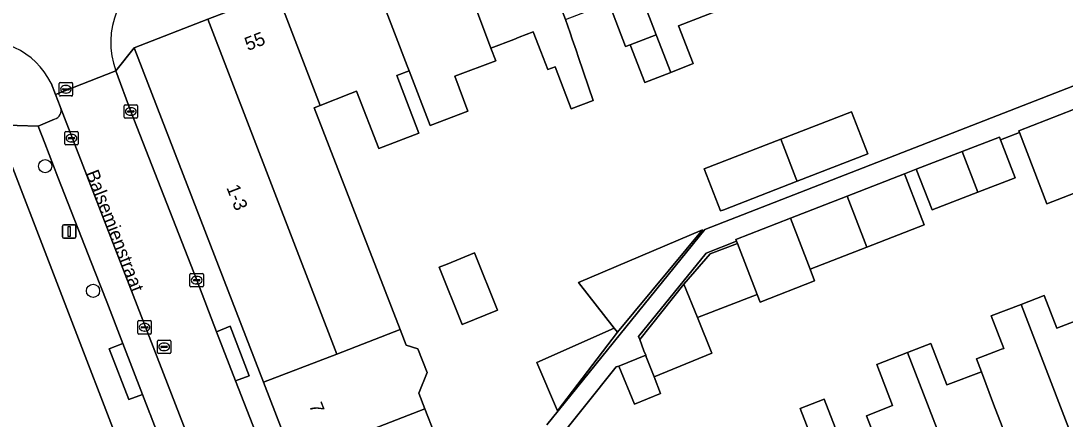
# Model space of a CAD drawing. Extents: x 161692 to 162379, y 380760 to 381678.
# Drawn here: x 161835.2 to 161912.8, y 381153.5 to 381183.1 of the extents above; entities that cross this region are included whole.
import ezdxf

# ---------------------------------------------------------------- set-up
doc = ezdxf.new("R2010")
doc.units = 0
for name, color, linetype in [('IMGEO_Boom', 7, 'Continuous'), ('IMGEO_Erf', 7, 'Continuous'), ('IMGEO_Kolk', 7, 'Continuous'), ('IMGEO_Lichtmast', 7, 'Continuous'), ('IMGEO_Openbare_ruimte_label', 7, 'Continuous'), ('IMGEO_Pand', 7, 'Continuous'), ('IMGEO_Pand_nummerreeks', 7, 'Continuous'), ('IMGEO_Parkeervlak_open', 7, 'Continuous'), ('IMGEO_Rijbaan_lokaal_open', 7, 'Continuous'), ('IMGEO_Rioolput', 7, 'Continuous'), ('IMGEO_Voetpad_open', 7, 'Continuous')]:
    doc.layers.add(name, color=color, linetype=linetype)

msp = doc.modelspace()

# ---------------------------------------------------------------- linework, layer by layer
at = {"layer": 'IMGEO_Boom'}
for centre in [(161836.982, 381172.296), (161840.539, 381163.033)]:
    msp.add_circle(centre, 0.489, dxfattribs=at)
at = {"layer": 'IMGEO_Erf'}
for points in [[(161887.347, 381183.967), (161884.084, 381182.701), (161885.163, 381179.907), (161883.498, 381179.26), (161881.565, 381178.51), (161880.481, 381181.302), (161880.149, 381181.173), (161878.886, 381184.426)], [(161875.683, 381183.185), (161876.021, 381182.188), (161876.181, 381181.716), (161876.457, 381180.901), (161876.644, 381180.352), (161877.72, 381177.175), (161876.108, 381176.549), (161874.895, 381179.673), (161874.372, 381179.47), (161873.851, 381180.812), (161873.282, 381182.277), (161872.232, 381181.869), (161871.822, 381181.71), (161870.13, 381181.053), (161870.484, 381180.109), (161867.441, 381178.968), (161868.413, 381176.374), (161865.604, 381175.321), (161864.044, 381179.374), (161863.12, 381179.015), (161864.764, 381174.744), (161861.798, 381173.593), (161860.142, 381177.859), (161859.691, 381177.684), (161857.428, 381176.805), (161856.984, 381176.633), (161863.374, 381160.161), (161863.819, 381159.013), (161864.704, 381158.737), (161865.389, 381156.97), (161864.766, 381155.425), (161865.216, 381154.264), (161865.926, 381152.436)], [(161874.298, 381153.095), (161886.039, 381167.594), (161916.769, 381179.551)], [(161854.96, 381119.298), (161852.88, 381124.681), (161833.302, 381175.355), (161830.972, 381176.303), (161782.92, 381157.51), (161766.802, 381160.481), (161766.378, 381160.559)], [(161915.559, 381171.074), (161911.474, 381169.496), (161909.428, 381174.795), (161908.019, 381174.254), (161909.11, 381171.437), (161906.334, 381170.361), (161902.933, 381169.043), (161901.766, 381172.062), (161900.896, 381171.725), (161902.063, 381168.706), (161902.352, 381167.93), (161898.092, 381166.28), (161893.863, 381164.642), (161894.2, 381163.77), (161890.147, 381162.199), (161889.925, 381162.773), (161885.48, 381161.051), (161886.553, 381158.395), (161882.26, 381156.64), (161882.731, 381155.417), (161880.796, 381154.626), (161879.645, 381157.442), (161879.432, 381157.38), (161874.741, 381151.504)], [(161899.206, 381150.813), (161898.066, 381153.763), (161900.001, 381154.51), (161898.818, 381157.573), (161901.113, 381158.46), (161902.848, 381159.131), (161904.04, 381156.046), (161904.116, 381156.075), (161906.602, 381157.017), (161906.233, 381157.993), (161907.863, 381158.611), (161908.093, 381158.698), (161908.262, 381158.762), (161907.334, 381161.171), (161909.551, 381162.027), (161911.285, 381162.697), (161912.225, 381160.266), (161914.674, 381161.212)], [(161893.937, 381152.191), (161893.123, 381154.298), (161894.921, 381154.993), (161895.735, 381152.886)]]:
    msp.add_lwpolyline(points, dxfattribs=at)
for points in [[(161896.945, 381176.323), (161898.147, 381173.214), (161892.908, 381171.173), (161887.438, 381169.06), (161887.202, 381168.969), (161885.995, 381172.096), (161891.7, 381174.299)], [(161879.533, 381159.957), (161875.084, 381154.124), (161873.533, 381157.706), (161879.286, 381160.272), (161876.651, 381163.642), (161885.853, 381167.576)], [(161884.481, 381163.524), (161886.441, 381165.776), (161888.458, 381166.558), (161888.395, 381166.721), (161886.13, 381165.843), (161881.107, 381159.64), (161881.194, 381159.413)], [(161868.916, 381165.851), (161870.627, 381161.602), (161867.991, 381160.54), (161866.279, 381164.787), (161866.871, 381165.026)]]:
    msp.add_lwpolyline(points, close=True, dxfattribs=at)
at = {"layer": 'IMGEO_Kolk'}
for p, q in [((161842.847, 381175.926), (161842.847, 381176.778)), ((161842.922, 381176.852), (161843.774, 381176.852)), ((161843.848, 381176.778), (161843.848, 381175.926)), ((161843.106, 381176.346), (161843.106, 381176.358)), ((161843.544, 381176.309), (161843.146, 381176.309)), ((161843.149, 381176.395), (161843.547, 381176.395)), ((161843.358, 381176.072), (161843.333, 381176.072)), ((161843.335, 381176.632), (161843.36, 381176.632)), ((161843.59, 381176.358), (161843.59, 381176.346)), ((161843.774, 381175.852), (161842.922, 381175.852)), ((161838.438, 381173.943), (161838.438, 381174.795)), ((161838.513, 381174.869), (161839.365, 381174.869)), ((161838.926, 381174.649), (161838.951, 381174.649)), ((161839.439, 381174.795), (161839.439, 381173.943)), ((161839.365, 381173.869), (161838.513, 381173.869)), ((161838.697, 381174.363), (161838.697, 381174.375)), ((161839.135, 381174.326), (161838.737, 381174.326)), ((161838.74, 381174.412), (161839.138, 381174.412)), ((161838.949, 381174.089), (161838.924, 381174.089)), ((161839.181, 381174.375), (161839.181, 381174.363)), ((161847.746, 381163.4), (161847.746, 381164.252)), ((161847.821, 381164.326), (161848.673, 381164.326)), ((161848.005, 381163.82), (161848.005, 381163.832)), ((161848.443, 381163.783), (161848.045, 381163.783)), ((161848.048, 381163.869), (161848.446, 381163.869)), ((161848.234, 381164.106), (161848.259, 381164.106)), ((161848.489, 381163.832), (161848.489, 381163.82)), ((161848.747, 381164.252), (161848.747, 381163.4)), ((161848.673, 381163.326), (161847.821, 381163.326)), ((161848.257, 381163.546), (161848.232, 381163.546)), ((161843.871, 381159.902), (161843.871, 381160.754)), ((161843.946, 381160.828), (161844.798, 381160.828)), ((161844.359, 381160.608), (161844.384, 381160.608)), ((161844.872, 381160.754), (161844.872, 381159.902)), ((161844.798, 381159.828), (161843.946, 381159.828)), ((161844.13, 381160.322), (161844.13, 381160.334)), ((161844.568, 381160.285), (161844.17, 381160.285)), ((161844.173, 381160.371), (161844.571, 381160.371)), ((161844.382, 381160.048), (161844.357, 381160.048)), ((161844.614, 381160.334), (161844.614, 381160.322))]:
    msp.add_line(p, q, dxfattribs=at)
for points in [[(161842.847, 381175.926), (161842.847, 381176.778)], [(161842.922, 381176.852), (161843.774, 381176.852)], [(161843.848, 381176.778), (161843.848, 381175.926)], [(161843.774, 381175.852), (161842.922, 381175.852)], [(161838.438, 381173.943), (161838.438, 381174.795)], [(161838.513, 381174.869), (161839.365, 381174.869)], [(161839.439, 381174.795), (161839.439, 381173.943)], [(161839.365, 381173.869), (161838.513, 381173.869)], [(161847.746, 381163.4), (161847.746, 381164.252)], [(161847.821, 381164.326), (161848.673, 381164.326)], [(161848.747, 381164.252), (161848.747, 381163.4)], [(161848.673, 381163.326), (161847.821, 381163.326)], [(161843.871, 381159.902), (161843.871, 381160.754)], [(161843.946, 381160.828), (161844.798, 381160.828)], [(161844.872, 381160.754), (161844.872, 381159.902)], [(161844.798, 381159.828), (161843.946, 381159.828)]]:
    msp.add_lwpolyline(points, dxfattribs=at)
for centre, radius, start, end in [((161842.924, 381176.776), 0.0765, 91.55205, 178.44795), ((161842.924, 381176.776), 0.0765, 91.55205, 178.44795), ((161843.772, 381176.776), 0.0765, 1.55205, 88.44795), ((161843.772, 381176.776), 0.0765, 1.55205, 88.44795), ((161843.146, 381176.355), 0.0403, 85.87752, 175.75265), ((161843.143, 381176.345), 0.0366, 178.93798, 274.71019), ((161843.547, 381176.352), 0.043, 264.86636, 352.45326), ((161843.551, 381176.357), 0.0386, 1.73085, 96.63898), ((161842.924, 381175.928), 0.0765, 181.55205, 268.44795), ((161842.924, 381175.928), 0.0765, 181.55205, 268.44795), ((161843.772, 381175.928), 0.0765, 271.55205, 358.44795), ((161843.772, 381175.928), 0.0765, 271.55205, 358.44795), ((161838.515, 381174.793), 0.0765, 91.55205, 178.44795), ((161838.515, 381174.793), 0.0765, 91.55205, 178.44795), ((161839.363, 381174.793), 0.0765, 1.55205, 88.44795), ((161839.363, 381174.793), 0.0765, 1.55205, 88.44795), ((161838.515, 381173.945), 0.0765, 181.55205, 268.44795), ((161838.515, 381173.945), 0.0765, 181.55205, 268.44795), ((161838.737, 381174.372), 0.0403, 85.87752, 175.75265), ((161838.734, 381174.362), 0.0366, 178.93798, 274.71019), ((161839.138, 381174.369), 0.043, 264.86636, 352.45326), ((161839.142, 381174.374), 0.0386, 1.73085, 96.63898), ((161839.363, 381173.945), 0.0765, 271.55205, 358.44795), ((161839.363, 381173.945), 0.0765, 271.55205, 358.44795), ((161847.823, 381164.25), 0.0765, 91.55205, 178.44795), ((161847.823, 381164.25), 0.0765, 91.55205, 178.44795), ((161848.045, 381163.829), 0.0403, 85.87752, 175.75265), ((161848.042, 381163.819), 0.0366, 178.93798, 274.71019), ((161848.446, 381163.826), 0.043, 264.86636, 352.45326), ((161848.45, 381163.831), 0.0386, 1.73085, 96.63898), ((161848.671, 381164.25), 0.0765, 1.55205, 88.44795), ((161848.671, 381164.25), 0.0765, 1.55205, 88.44795), ((161847.823, 381163.402), 0.0765, 181.55205, 268.44795), ((161847.823, 381163.402), 0.0765, 181.55205, 268.44795), ((161848.671, 381163.402), 0.0765, 271.55205, 358.44795), ((161848.671, 381163.402), 0.0765, 271.55205, 358.44795), ((161843.948, 381160.752), 0.0765, 91.55205, 178.44795), ((161843.948, 381160.752), 0.0765, 91.55205, 178.44795), ((161844.796, 381160.752), 0.0765, 1.55205, 88.44795), ((161844.796, 381160.752), 0.0765, 1.55205, 88.44795), ((161843.948, 381159.904), 0.0765, 181.55205, 268.44795), ((161843.948, 381159.904), 0.0765, 181.55205, 268.44795), ((161844.17, 381160.331), 0.0403, 85.87752, 175.75265), ((161844.167, 381160.321), 0.0366, 178.93798, 274.71019), ((161844.571, 381160.328), 0.043, 264.86636, 352.45326), ((161844.575, 381160.333), 0.0386, 1.73085, 96.63898), ((161844.796, 381159.904), 0.0765, 271.55205, 358.44795), ((161844.796, 381159.904), 0.0765, 271.55205, 358.44795)]:
    msp.add_arc(centre, radius, start, end, dxfattribs=at)
for centre, major_axis, ratio, start_param, end_param in [((161843.334, 381176.352), (-0.387, 0.002), 0.722429, 4.712389, 7.853982), ((161843.359, 381176.352), (-0.39, 0.002), 0.717154, 1.570796, 4.712389), ((161838.925, 381174.369), (-0.387, 0.002), 0.722429, 4.712389, 7.853982), ((161838.95, 381174.369), (-0.39, 0.002), 0.717154, 1.570796, 4.712389), ((161848.233, 381163.826), (-0.387, 0.002), 0.722429, 4.712389, 7.853982), ((161848.258, 381163.826), (-0.39, 0.002), 0.717154, 1.570796, 4.712389), ((161844.358, 381160.328), (-0.387, 0.002), 0.722429, 4.712389, 7.853982), ((161844.383, 381160.328), (-0.39, 0.002), 0.717154, 1.570796, 4.712389)]:
    msp.add_ellipse(centre, major_axis=major_axis, ratio=ratio, start_param=start_param, end_param=end_param, dxfattribs=at)
at = {"layer": 'IMGEO_Lichtmast'}
for p, q in [((161838.274, 381167.04), (161838.274, 381167.84)), ((161838.274, 381167.84), (161838.274, 381167.04)), ((161838.374, 381167.94), (161839.164, 381167.94)), ((161839.164, 381167.94), (161838.374, 381167.94)), ((161839.264, 381167.84), (161839.264, 381167.04)), ((161839.264, 381167.04), (161839.264, 381167.84)), ((161839.164, 381166.94), (161838.374, 381166.94)), ((161838.374, 381166.94), (161839.164, 381166.94))]:
    msp.add_line(p, q, dxfattribs=at)
msp.add_lwpolyline([(161838.694, 381167.815), (161838.844, 381167.815), (161838.844, 381167.065), (161838.694, 381167.065), (161838.694, 381167.815)], dxfattribs=at)
for centre, start, end in [((161838.374, 381167.84), 90, 180), ((161838.374, 381167.84), 90, 180), ((161839.164, 381167.84), 0, 90), ((161839.164, 381167.84), 360, 90), ((161838.374, 381167.04), 180, 270), ((161838.374, 381167.04), 180, 270), ((161839.164, 381167.04), 270, 0), ((161839.164, 381167.04), 270, 0)]:
    msp.add_arc(centre, 0.1, start, end, dxfattribs=at)
at = {"layer": 'IMGEO_Pand'}
for points in [[(161883.425, 381195.727), (161882.9, 381195.524), (161882.325, 381195.986), (161880.061, 381195.107), (161879.937, 381194.305), (161877.981, 381193.546), (161882.172, 381182.693), (161882.419, 381182.054), (161883.498, 381179.26), (161885.163, 381179.907), (161884.084, 381182.701), (161887.347, 381183.967), (161886.094, 381187.199), (161886.637, 381187.41)], [(161877.981, 381193.546), (161875.697, 381192.659), (161875.012, 381193.209), (161872.965, 381192.415), (161872.83, 381191.539), (161872.505, 381191.413), (161875.683, 381183.185), (161877.356, 381183.833), (161877.67, 381183.955), (161878.662, 381184.339), (161878.886, 381184.426), (161880.149, 381181.173), (161880.481, 381181.302), (161882.419, 381182.054), (161882.172, 381182.693)], [(161872.505, 381191.413), (161870.281, 381190.549), (161869.541, 381191.144), (161866.752, 381190.062), (161870.13, 381181.053), (161871.822, 381181.71), (161872.232, 381181.869), (161873.282, 381182.277), (161873.851, 381180.812), (161874.372, 381179.47), (161874.895, 381179.673), (161876.108, 381176.549), (161877.72, 381177.175), (161876.644, 381180.352), (161876.457, 381180.901), (161876.181, 381181.716), (161876.021, 381182.188), (161875.683, 381183.185)], [(161866.752, 381190.062), (161860.818, 381187.759), (161863.904, 381179.738), (161864.044, 381179.374), (161865.604, 381175.321), (161868.413, 381176.374), (161867.441, 381178.968), (161870.484, 381180.109), (161870.13, 381181.053)], [(161860.818, 381187.759), (161854.202, 381185.191), (161857.428, 381176.805), (161859.691, 381177.684), (161860.142, 381177.859), (161861.798, 381173.593), (161864.764, 381174.744), (161863.12, 381179.015), (161864.044, 381179.374), (161863.904, 381179.738)], [(161849.069, 381183.199), (161858.668, 381158.344), (161863.374, 381160.161), (161856.984, 381176.633), (161857.428, 381176.805), (161854.202, 381185.191)], [(161853.223, 381156.241), (161858.668, 381158.344), (161849.069, 381183.199), (161843.607, 381181.079)], [(161882.419, 381182.054), (161880.481, 381181.302), (161881.565, 381178.51), (161883.498, 381179.26)], [(161891.7, 381174.299), (161891.868, 381173.864), (161892.816, 381171.412), (161892.908, 381171.173), (161898.147, 381173.214), (161896.945, 381176.323)], [(161913.463, 381176.501), (161909.378, 381174.923), (161909.428, 381174.795), (161911.474, 381169.496), (161915.559, 381171.074)], [(161908.019, 381174.254), (161907.941, 381174.454), (161905.169, 381173.38), (161906.334, 381170.361), (161909.11, 381171.437)], [(161891.868, 381173.864), (161891.7, 381174.299), (161885.995, 381172.096), (161887.202, 381168.969), (161887.438, 381169.06), (161892.908, 381171.173), (161892.816, 381171.412)], [(161905.169, 381173.38), (161901.766, 381172.062), (161902.933, 381169.043), (161906.334, 381170.361)], [(161900.896, 381171.725), (161896.628, 381170.07), (161898.092, 381166.28), (161902.352, 381167.93), (161902.063, 381168.706)], [(161896.628, 381170.07), (161892.399, 381168.431), (161893.863, 381164.642), (161898.092, 381166.28)], [(161892.399, 381168.431), (161888.341, 381166.859), (161888.395, 381166.721), (161888.458, 381166.558), (161889.925, 381162.773), (161890.147, 381162.199), (161894.2, 381163.77), (161893.863, 381164.642)], [(161879.286, 381160.272), (161879.533, 381159.957), (161885.853, 381167.576), (161876.651, 381163.642)], [(161888.458, 381166.558), (161886.441, 381165.776), (161884.481, 381163.524), (161885.48, 381161.051), (161889.925, 381162.773)], [(161866.279, 381164.787), (161867.991, 381160.54), (161870.627, 381161.602), (161868.916, 381165.851), (161866.871, 381165.026)], [(161885.48, 381161.051), (161884.481, 381163.524), (161881.194, 381159.413), (161881.511, 381158.588), (161881.638, 381158.257), (161881.681, 381158.146), (161882.26, 381156.64), (161886.553, 381158.395)], [(161909.551, 381162.027), (161907.334, 381161.171), (161908.262, 381158.762), (161908.093, 381158.698), (161907.863, 381158.611), (161906.233, 381157.993), (161906.602, 381157.017), (161907.51, 381154.621), (161910.252, 381147.53), (161914.14, 381149.033), (161914.356, 381148.475), (161914.726, 381148.618)], [(161914.674, 381161.212), (161912.225, 381160.266), (161911.285, 381162.697), (161909.551, 381162.027), (161914.726, 381148.618), (161918.913, 381150.237), (161916.157, 381157.372)], [(161853.223, 381156.241), (161855.451, 381150.483), (161865.216, 381154.264), (161864.766, 381155.425), (161865.389, 381156.97), (161864.704, 381158.737), (161863.819, 381159.013), (161863.374, 381160.161), (161858.668, 381158.344)], [(161879.533, 381159.957), (161879.286, 381160.272), (161873.533, 381157.706), (161875.084, 381154.124)], [(161906.602, 381157.017), (161904.116, 381156.075), (161904.04, 381156.046), (161902.848, 381159.131), (161901.113, 381158.46), (161902.3, 381155.387), (161906.184, 381145.333), (161910.462, 381146.987), (161910.252, 381147.53), (161907.51, 381154.621)], [(161882.26, 381156.64), (161881.681, 381158.146), (161881.638, 381158.257), (161879.645, 381157.442), (161880.796, 381154.626), (161882.731, 381155.417)], [(161906.184, 381145.333), (161902.3, 381155.387), (161901.113, 381158.46), (161898.818, 381157.573), (161900.001, 381154.51), (161898.066, 381153.763), (161899.206, 381150.813), (161901.955, 381143.698)], [(161865.216, 381154.264), (161855.451, 381150.483), (161857.147, 381146.103), (161858.29, 381146.546), (161858.163, 381146.874), (161862.825, 381148.683), (161864.611, 381149.376), (161866.786, 381150.22), (161866.117, 381151.943), (161865.926, 381152.436)], [(161897.834, 381142.104), (161901.955, 381143.698), (161899.206, 381150.813), (161896.884, 381149.915), (161895.735, 381152.886), (161894.921, 381154.993), (161893.123, 381154.298), (161893.937, 381152.191)]]:
    msp.add_lwpolyline(points, close=True, dxfattribs=at)
at = {"layer": 'IMGEO_Parkeervlak_open'}
for points in [[(161855.826, 381131.012), (161838.128, 381176.641)], [(161837.683, 381175.784), (161836.452, 381175.254), (161836.947, 381173.989), (161837.932, 381171.471), (161840.67, 381164.477), (161841.558, 381162.207), (161842.766, 381159.12), (161844.228, 381155.33), (161844.771, 381153.925), (161844.787, 381153.884), (161845.637, 381151.683), (161849.329, 381142.123), (161850.18, 381139.921), (161853.234, 381132.015), (161853.712, 381130.777), (161854.94, 381131.274)]]:
    msp.add_lwpolyline(points, dxfattribs=at)
msp.add_arc((161837.48, 381176.433), 0.68, 287.35328, 17.76524, dxfattribs=at)
at = {"layer": 'IMGEO_Rijbaan_lokaal_open'}
for points in [[(161837.414, 381178.445), (161837.736, 381177.625), (161842.227, 381179.366)], [(161851.128, 381156.352), (161849.716, 381159.992), (161848.247, 381163.826), (161843.348, 381176.352), (161842.227, 381179.366), (161837.736, 381177.625), (161838.086, 381176.732), (161838.128, 381176.641), (161855.826, 381131.012)], [(161855.889, 381130.847), (161856.238, 381129.843), (161860.811, 381131.453), (161859.931, 381133.78), (161854.512, 381147.731), (161851.128, 381156.352)]]:
    msp.add_lwpolyline(points, dxfattribs=at)
for centre, radius, start, end in [((161847.948, 381181.477), 6.098, 114.76344, 200.24814), ((161832.316, 381175.959), 5.672, 26.00177, 103.52384)]:
    msp.add_arc(centre, radius, start, end, dxfattribs=at)
at = {"layer": 'IMGEO_Rioolput'}
for p, q in [((161838.02, 381177.577), (161838.02, 381178.429)), ((161838.095, 381178.503), (161838.947, 381178.503)), ((161839.021, 381178.429), (161839.021, 381177.577)), ((161838.279, 381177.997), (161838.279, 381178.009)), ((161838.717, 381177.96), (161838.319, 381177.96)), ((161838.322, 381178.046), (161838.72, 381178.046)), ((161838.531, 381177.723), (161838.506, 381177.723)), ((161838.508, 381178.283), (161838.533, 381178.283)), ((161838.763, 381178.009), (161838.763, 381177.997)), ((161838.947, 381177.503), (161838.095, 381177.503)), ((161845.324, 381158.453), (161845.324, 381159.305)), ((161845.399, 381159.379), (161846.251, 381159.379)), ((161845.626, 381158.922), (161846.024, 381158.922)), ((161845.812, 381159.159), (161845.837, 381159.159)), ((161846.325, 381159.305), (161846.325, 381158.453)), ((161846.251, 381158.379), (161845.399, 381158.379)), ((161845.583, 381158.873), (161845.583, 381158.885)), ((161846.021, 381158.836), (161845.623, 381158.836)), ((161845.835, 381158.599), (161845.81, 381158.599)), ((161846.067, 381158.885), (161846.067, 381158.873))]:
    msp.add_line(p, q, dxfattribs=at)
for points in [[(161838.02, 381177.577), (161838.02, 381178.429)], [(161838.095, 381178.503), (161838.947, 381178.503)], [(161839.021, 381178.429), (161839.021, 381177.577)], [(161838.947, 381177.503), (161838.095, 381177.503)], [(161845.324, 381158.453), (161845.324, 381159.305)], [(161845.399, 381159.379), (161846.251, 381159.379)], [(161846.325, 381159.305), (161846.325, 381158.453)], [(161846.251, 381158.379), (161845.399, 381158.379)]]:
    msp.add_lwpolyline(points, dxfattribs=at)
for centre, radius, start, end in [((161838.097, 381178.427), 0.0765, 91.55205, 178.44795), ((161838.097, 381178.427), 0.0765, 91.55205, 178.44795), ((161838.945, 381178.427), 0.0765, 1.55205, 88.44795), ((161838.945, 381178.427), 0.0765, 1.55205, 88.44795), ((161838.097, 381177.579), 0.0765, 181.55205, 268.44795), ((161838.097, 381177.579), 0.0765, 181.55205, 268.44795), ((161838.319, 381178.006), 0.0403, 85.87752, 175.75265), ((161838.316, 381177.996), 0.0366, 178.93798, 274.71019), ((161838.72, 381178.003), 0.043, 264.86636, 352.45326), ((161838.724, 381178.008), 0.0386, 1.73085, 96.63898), ((161838.945, 381177.579), 0.0765, 271.55205, 358.44795), ((161838.945, 381177.579), 0.0765, 271.55205, 358.44795), ((161845.401, 381159.303), 0.0765, 91.55205, 178.44795), ((161845.401, 381159.303), 0.0765, 91.55205, 178.44795), ((161845.623, 381158.882), 0.0403, 85.87752, 175.75265), ((161846.028, 381158.884), 0.0386, 1.73085, 96.63898), ((161846.249, 381159.303), 0.0765, 1.55205, 88.44795), ((161846.249, 381159.303), 0.0765, 1.55205, 88.44795), ((161845.401, 381158.455), 0.0765, 181.55205, 268.44795), ((161845.401, 381158.455), 0.0765, 181.55205, 268.44795), ((161845.62, 381158.872), 0.0366, 178.93798, 274.71019), ((161846.024, 381158.879), 0.043, 264.86636, 352.45326), ((161846.249, 381158.455), 0.0765, 271.55205, 358.44795), ((161846.249, 381158.455), 0.0765, 271.55205, 358.44795)]:
    msp.add_arc(centre, radius, start, end, dxfattribs=at)
for centre, major_axis, ratio, start_param, end_param in [((161838.507, 381178.003), (-0.387, 0.002), 0.722429, 4.712389, 7.853982), ((161838.532, 381178.003), (-0.39, 0.002), 0.717154, 1.570796, 4.712389), ((161845.811, 381158.879), (-0.387, 0.002), 0.722429, 4.712389, 7.853982), ((161845.836, 381158.879), (-0.39, 0.002), 0.717154, 1.570796, 4.712389)]:
    msp.add_ellipse(centre, major_axis=major_axis, ratio=ratio, start_param=start_param, end_param=end_param, dxfattribs=at)
at = {"layer": 'IMGEO_Voetpad_open'}
for points in [[(161842.227, 381179.366), (161843.607, 381181.079), (161849.069, 381183.199), (161854.202, 381185.191), (161860.818, 381187.759)], [(161853.223, 381156.241), (161843.607, 381181.079), (161842.227, 381179.366), (161843.348, 381176.352), (161848.247, 381163.826), (161849.716, 381159.992), (161850.733, 381160.401), (161852.146, 381156.727), (161851.128, 381156.352), (161854.512, 381147.731), (161859.931, 381133.78), (161860.811, 381131.453), (161861.112, 381130.676)], [(161916.769, 381179.551), (161886.039, 381167.594), (161874.298, 381153.095)], [(161838.128, 381176.641), (161838.086, 381176.732), (161837.736, 381177.625), (161837.414, 381178.445)], [(161766.378, 381160.559), (161766.802, 381160.481), (161782.92, 381157.51), (161830.972, 381176.303), (161833.302, 381175.355), (161836.452, 381175.254), (161837.683, 381175.784)], [(161874.741, 381151.504), (161879.432, 381157.38), (161879.645, 381157.442), (161881.638, 381158.257), (161881.511, 381158.588), (161881.194, 381159.413), (161881.107, 381159.64), (161886.13, 381165.843), (161888.395, 381166.721), (161888.341, 381166.859), (161892.399, 381168.431), (161896.628, 381170.07), (161900.896, 381171.725), (161901.766, 381172.062), (161905.169, 381173.38), (161907.941, 381174.454), (161908.019, 381174.254), (161909.428, 381174.795), (161909.378, 381174.923), (161913.463, 381176.501)], [(161854.94, 381131.274), (161853.712, 381130.777), (161853.234, 381132.015), (161850.18, 381139.921), (161849.329, 381142.123), (161845.637, 381151.683), (161844.787, 381153.884), (161844.771, 381153.925), (161844.228, 381155.33), (161843.196, 381154.954), (161841.747, 381158.726), (161842.766, 381159.12), (161841.558, 381162.207), (161840.67, 381164.477), (161837.932, 381171.471), (161836.947, 381173.989), (161836.452, 381175.254), (161833.302, 381175.355), (161852.88, 381124.681), (161854.96, 381119.298), (161849.813, 381072.956)], [(161867.569, 381126.828), (161864.944, 381129.405), (161863.314, 381130.126), (161857.799, 381144.387), (161857.147, 381146.103), (161855.451, 381150.483), (161853.223, 381156.241)]]:
    msp.add_lwpolyline(points, dxfattribs=at)
for points in [[(161849.716, 381159.992), (161851.128, 381156.352), (161852.146, 381156.727), (161850.733, 381160.401)], [(161842.766, 381159.12), (161841.747, 381158.726), (161843.196, 381154.954), (161844.228, 381155.33)]]:
    msp.add_lwpolyline(points, close=True, dxfattribs=at)
for centre, radius, start, end in [((161847.948, 381181.477), 6.098, 114.76344, 200.24814), ((161832.316, 381175.959), 5.672, 26.00177, 103.52384), ((161837.48, 381176.433), 0.68, 287.35328, 17.76524)]:
    msp.add_arc(centre, radius, start, end, dxfattribs=at)

# ---------------------------------------------------------------- texts
at = {"layer": 'IMGEO_Openbare_ruimte_label'}
msp.add_text('Balsemienstraat', height=1, rotation=291.15265, dxfattribs=at).set_placement((161839.971, 381171.785))
at = {"layer": 'IMGEO_Pand_nummerreeks'}
for s, rotation, p in [('55', 21.19591, (161852.051, 381180.839)), ('1-3', 291.39898, (161850.441, 381170.703)), ('7', 291.17759, (161856.586, 381154.529))]:
    msp.add_text(s, height=1, rotation=rotation, dxfattribs=at).set_placement(p)

doc.saveas('drawing.dxf')
